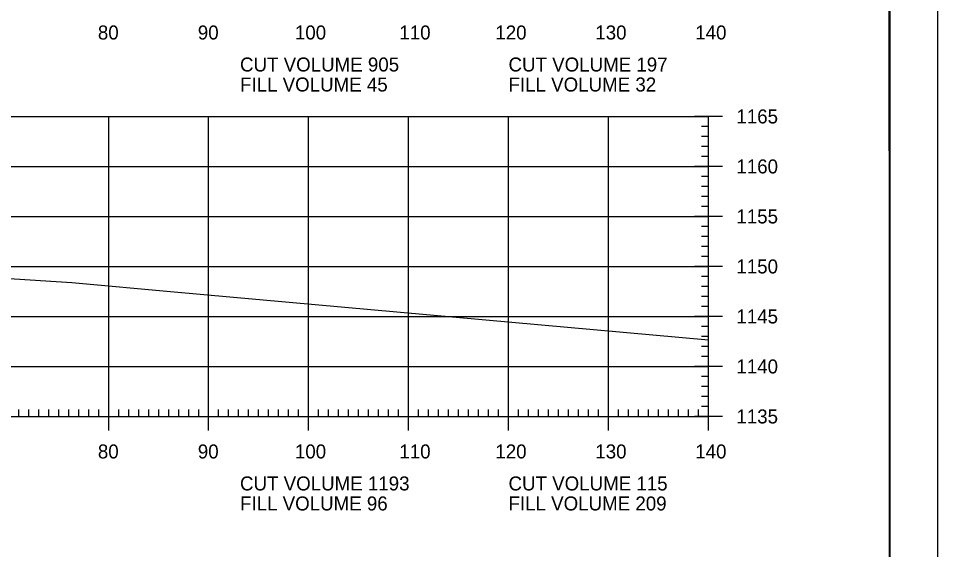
# Model space of a CAD drawing. Extents: x 1322838 to 1324533, y 339903 to 351025.
# Drawn here: x 1323774.7 to 1323866.6, y 342569.8 to 342623 of the extents above; entities that cross this region are included whole.
import ezdxf

# ---------------------------------------------------------------- set-up
doc = ezdxf.new("R2010")
doc.units = 0
for name, color, linetype in [('R_Axis', 7, 'Continuous'), ('R_Axis Annot', 7, 'Continuous'), ('R_Border', 7, 'Continuous'), ('R_Exist Surface', 7, 'Continuous'), ('R_Grid', 7, 'Continuous'), ('R_No Plot', 7, 'Continuous')]:
    doc.layers.add(name, color=color, linetype=linetype)

msp = doc.modelspace()

# ---------------------------------------------------------------- linework, layer by layer
at = {"layer": 'R_Axis'}
for p, q in [((1323845.115, 342613.158), (1323842.315, 342613.158)), ((1323843.715, 342583.158), (1323843.715, 342613.158)), ((1323843.715, 342612.158), (1323843.015, 342612.158)), ((1323843.715, 342611.158), (1323843.015, 342611.158)), ((1323843.715, 342610.158), (1323843.015, 342610.158)), ((1323843.715, 342609.158), (1323843.015, 342609.158)), ((1323845.115, 342608.158), (1323842.315, 342608.158)), ((1323843.715, 342607.158), (1323843.015, 342607.158)), ((1323843.715, 342606.158), (1323843.015, 342606.158)), ((1323843.715, 342605.158), (1323843.015, 342605.158)), ((1323843.715, 342604.158), (1323843.015, 342604.158)), ((1323845.115, 342603.158), (1323842.315, 342603.158)), ((1323843.715, 342602.158), (1323843.015, 342602.158)), ((1323843.715, 342601.158), (1323843.015, 342601.158)), ((1323843.715, 342600.158), (1323843.015, 342600.158)), ((1323843.715, 342599.158), (1323843.015, 342599.158)), ((1323845.115, 342598.158), (1323842.315, 342598.158)), ((1323843.715, 342597.158), (1323843.015, 342597.158)), ((1323843.715, 342596.158), (1323843.015, 342596.158)), ((1323843.715, 342595.158), (1323843.015, 342595.158)), ((1323843.715, 342594.158), (1323843.015, 342594.158)), ((1323845.115, 342593.158), (1323842.315, 342593.158)), ((1323843.715, 342592.158), (1323843.015, 342592.158)), ((1323843.715, 342591.158), (1323843.015, 342591.158)), ((1323843.715, 342590.158), (1323843.015, 342590.158)), ((1323843.715, 342589.158), (1323843.015, 342589.158)), ((1323845.115, 342588.158), (1323842.315, 342588.158)), ((1323843.715, 342587.158), (1323843.015, 342587.158)), ((1323843.715, 342586.158), (1323843.015, 342586.158)), ((1323843.715, 342585.158), (1323843.015, 342585.158)), ((1323783.715, 342581.758), (1323783.715, 342584.558)), ((1323793.715, 342581.758), (1323793.715, 342584.558)), ((1323803.715, 342581.758), (1323803.715, 342584.558)), ((1323813.715, 342581.758), (1323813.715, 342584.558)), ((1323823.715, 342581.758), (1323823.715, 342584.558)), ((1323833.715, 342581.758), (1323833.715, 342584.558)), ((1323843.715, 342584.158), (1323843.015, 342584.158)), ((1323843.715, 342581.758), (1323843.715, 342584.558)), ((1323563.715, 342583.158), (1323843.715, 342583.158)), ((1323774.715, 342583.158), (1323774.715, 342583.858)), ((1323775.715, 342583.158), (1323775.715, 342583.858)), ((1323776.715, 342583.158), (1323776.715, 342583.858)), ((1323777.715, 342583.158), (1323777.715, 342583.858)), ((1323778.715, 342583.158), (1323778.715, 342583.858)), ((1323779.715, 342583.158), (1323779.715, 342583.858)), ((1323780.715, 342583.158), (1323780.715, 342583.858)), ((1323781.715, 342583.158), (1323781.715, 342583.858)), ((1323782.715, 342583.158), (1323782.715, 342583.858)), ((1323784.715, 342583.158), (1323784.715, 342583.858)), ((1323785.715, 342583.158), (1323785.715, 342583.858)), ((1323786.715, 342583.158), (1323786.715, 342583.858)), ((1323787.715, 342583.158), (1323787.715, 342583.858)), ((1323788.715, 342583.158), (1323788.715, 342583.858)), ((1323789.715, 342583.158), (1323789.715, 342583.858)), ((1323790.715, 342583.158), (1323790.715, 342583.858)), ((1323791.715, 342583.158), (1323791.715, 342583.858)), ((1323792.715, 342583.158), (1323792.715, 342583.858)), ((1323794.715, 342583.158), (1323794.715, 342583.858)), ((1323795.715, 342583.158), (1323795.715, 342583.858)), ((1323796.715, 342583.158), (1323796.715, 342583.858)), ((1323797.715, 342583.158), (1323797.715, 342583.858)), ((1323798.715, 342583.158), (1323798.715, 342583.858)), ((1323799.715, 342583.158), (1323799.715, 342583.858)), ((1323800.715, 342583.158), (1323800.715, 342583.858)), ((1323801.715, 342583.158), (1323801.715, 342583.858)), ((1323802.715, 342583.158), (1323802.715, 342583.858)), ((1323804.715, 342583.158), (1323804.715, 342583.858)), ((1323805.715, 342583.158), (1323805.715, 342583.858)), ((1323806.715, 342583.158), (1323806.715, 342583.858)), ((1323807.715, 342583.158), (1323807.715, 342583.858)), ((1323808.715, 342583.158), (1323808.715, 342583.858)), ((1323809.715, 342583.158), (1323809.715, 342583.858)), ((1323810.715, 342583.158), (1323810.715, 342583.858)), ((1323811.715, 342583.158), (1323811.715, 342583.858)), ((1323812.715, 342583.158), (1323812.715, 342583.858)), ((1323814.715, 342583.158), (1323814.715, 342583.858)), ((1323815.715, 342583.158), (1323815.715, 342583.858)), ((1323816.715, 342583.158), (1323816.715, 342583.858)), ((1323817.715, 342583.158), (1323817.715, 342583.858)), ((1323818.715, 342583.158), (1323818.715, 342583.858)), ((1323819.715, 342583.158), (1323819.715, 342583.858)), ((1323820.715, 342583.158), (1323820.715, 342583.858)), ((1323821.715, 342583.158), (1323821.715, 342583.858)), ((1323822.715, 342583.158), (1323822.715, 342583.858)), ((1323824.715, 342583.158), (1323824.715, 342583.858)), ((1323825.715, 342583.158), (1323825.715, 342583.858)), ((1323826.715, 342583.158), (1323826.715, 342583.858)), ((1323827.715, 342583.158), (1323827.715, 342583.858)), ((1323828.715, 342583.158), (1323828.715, 342583.858)), ((1323829.715, 342583.158), (1323829.715, 342583.858)), ((1323830.715, 342583.158), (1323830.715, 342583.858)), ((1323831.715, 342583.158), (1323831.715, 342583.858)), ((1323832.715, 342583.158), (1323832.715, 342583.858)), ((1323834.715, 342583.158), (1323834.715, 342583.858)), ((1323835.715, 342583.158), (1323835.715, 342583.858)), ((1323836.715, 342583.158), (1323836.715, 342583.858)), ((1323837.715, 342583.158), (1323837.715, 342583.858)), ((1323838.715, 342583.158), (1323838.715, 342583.858)), ((1323839.715, 342583.158), (1323839.715, 342583.858)), ((1323840.715, 342583.158), (1323840.715, 342583.858)), ((1323841.715, 342583.158), (1323841.715, 342583.858)), ((1323845.115, 342583.158), (1323842.315, 342583.158)), ((1323842.715, 342583.158), (1323842.715, 342583.858))]:
    msp.add_line(p, q, dxfattribs=at)
at = {"layer": 'R_Border'}
msp.add_line((1323861.895, 342467.158), (1323861.895, 342672.618), dxfattribs=at)
at = {"layer": 'R_Exist Surface'}
msp.add_lwpolyline([(1323760.182, 342597.81), (1323780.01, 342596.568), (1323790.269, 342595.624), (1323843.715, 342590.807)], dxfattribs=at)
at = {"layer": 'R_Grid'}
for p, q in [((1323563.715, 342613.158), (1323843.715, 342613.158)), ((1323783.715, 342583.158), (1323783.715, 342613.158)), ((1323793.715, 342583.158), (1323793.715, 342613.158)), ((1323803.715, 342583.158), (1323803.715, 342613.158)), ((1323813.715, 342583.158), (1323813.715, 342613.158)), ((1323823.715, 342583.158), (1323823.715, 342613.158)), ((1323833.715, 342583.158), (1323833.715, 342613.158)), ((1323843.715, 342583.158), (1323843.715, 342613.158)), ((1323563.715, 342608.158), (1323843.715, 342608.158)), ((1323563.715, 342603.158), (1323843.715, 342603.158)), ((1323563.715, 342598.158), (1323843.715, 342598.158)), ((1323563.715, 342593.158), (1323843.715, 342593.158)), ((1323563.715, 342588.158), (1323843.715, 342588.158)), ((1323563.715, 342583.158), (1323843.715, 342583.158))]:
    msp.add_line(p, q, dxfattribs=at)
at = {"layer": 'R_No Plot'}
for points in [[(1323533.308, 342676.513), (1323866.648, 342676.513), (1323866.648, 342463.175), (1323533.308, 342463.175)], [(1323779.635, 342672.618), (1323799.255, 342672.618), (1323799.255, 342662.738), (1323815.368, 342662.738), (1323838.567, 342662.738), (1323838.567, 342630.068), (1323861.775, 342630.068), (1323861.895, 342467.158), (1323545.715, 342467.158), (1323545.715, 342672.618)]]:
    msp.add_lwpolyline(points, close=True, dxfattribs=at)

# ---------------------------------------------------------------- texts
at = {"layer": 'R_Axis Annot'}
for s, p in [('80', (1323782.63, 342620.851)), ('90', (1323792.63, 342620.851)), ('100', (1323802.343, 342620.851)), ('110', (1323812.795, 342620.851)), ('120', (1323822.398, 342620.851)), ('130', (1323832.398, 342620.851)), ('140', (1323842.398, 342620.851)), ('CUT VOLUME 905', (1323796.852, 342617.651)), ('CUT VOLUME 197', (1323823.715, 342617.651)), ('FILL VOLUME 45', (1323796.852, 342615.651)), ('FILL VOLUME 32', (1323823.715, 342615.651)), ('1165', (1323846.515, 342612.458)), ('1160', (1323846.515, 342607.458)), ('1155', (1323846.515, 342602.458)), ('1150', (1323846.515, 342597.458)), ('1145', (1323846.515, 342592.458)), ('1140', (1323846.515, 342587.458)), ('1135', (1323846.515, 342582.458)), ('80', (1323782.63, 342578.958)), ('90', (1323792.63, 342578.958)), ('100', (1323802.343, 342578.958)), ('110', (1323812.795, 342578.958)), ('120', (1323822.398, 342578.958)), ('130', (1323832.398, 342578.958)), ('140', (1323842.398, 342578.958)), ('CUT VOLUME 1193', (1323796.852, 342575.758)), ('CUT VOLUME 115', (1323823.715, 342575.758)), ('FILL VOLUME 96', (1323796.852, 342573.758)), ('FILL VOLUME 209', (1323823.715, 342573.758))]:
    msp.add_text(s, height=1.4, dxfattribs=at).set_placement(p)

doc.saveas('drawing.dxf')
